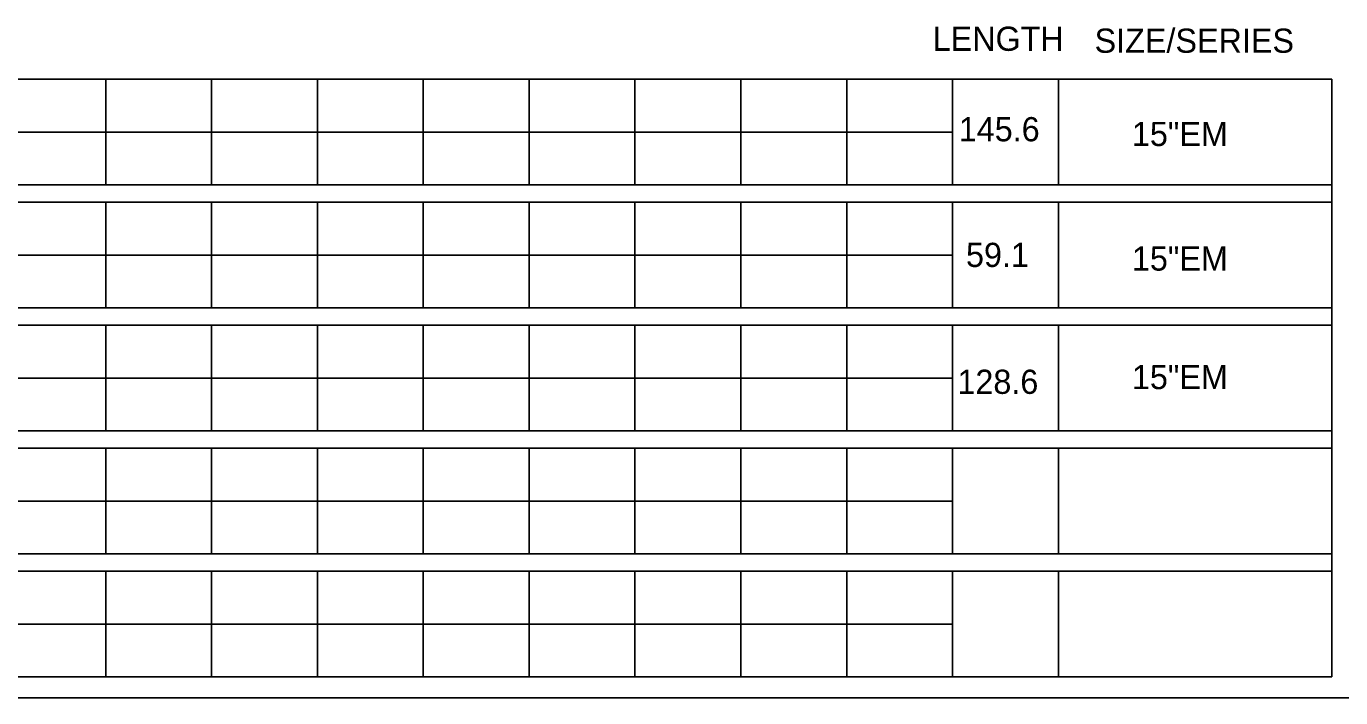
# Model space of a CAD drawing. Extents: x 10268147 to 10268469, y 2141099 to 2141204.
# Drawn here: x 10268191.41 to 10268229.47, y 2141157.19 to 2141176.62 of the extents above; entities that cross this region are included whole.
import ezdxf

# ---------------------------------------------------------------- set-up
doc = ezdxf.new("R2010")
doc.units = 0
for name, color, linetype in [('61', 7, 'Continuous'), ('GSDims', 7, 'Continuous'), ('North Arrow', 7, 'Continuous'), ('SheetLinesMisc2_dp', 7, 'Continuous'), ('TextMisc', 7, 'Continuous')]:
    doc.layers.add(name, color=color, linetype=linetype)

msp = doc.modelspace()

# ---------------------------------------------------------------- linework, layer by layer
at = {"layer": '61'}
for p, q in [((10268153.875, 2141175.094), (10268229.209, 2141175.094)), ((10268193.714, 2141175.094), (10268193.714, 2141172.034)), ((10268196.779, 2141175.094), (10268196.779, 2141172.034)), ((10268199.843, 2141175.094), (10268199.843, 2141172.034)), ((10268202.908, 2141175.094), (10268202.908, 2141172.034)), ((10268205.972, 2141175.094), (10268205.972, 2141172.034)), ((10268209.037, 2141175.094), (10268209.037, 2141172.034)), ((10268212.102, 2141175.094), (10268212.102, 2141172.034)), ((10268215.166, 2141175.094), (10268215.166, 2141172.034)), ((10268218.232, 2141175.094), (10268218.232, 2141172.034)), ((10268221.296, 2141175.094), (10268221.296, 2141172.034)), ((10268229.209, 2141157.796), (10268229.209, 2141175.094)), ((10268153.875, 2141173.564), (10268218.232, 2141173.564)), ((10268153.875, 2141172.034), (10268229.209, 2141172.034)), ((10268153.875, 2141171.535), (10268229.209, 2141171.535)), ((10268193.714, 2141171.535), (10268193.714, 2141168.475)), ((10268196.779, 2141171.535), (10268196.779, 2141168.475)), ((10268199.843, 2141171.535), (10268199.843, 2141168.475)), ((10268202.908, 2141171.535), (10268202.908, 2141168.475)), ((10268205.972, 2141171.535), (10268205.972, 2141168.475)), ((10268209.037, 2141171.535), (10268209.037, 2141168.475)), ((10268212.102, 2141171.535), (10268212.102, 2141168.475)), ((10268215.166, 2141171.535), (10268215.166, 2141168.475)), ((10268218.232, 2141171.535), (10268218.232, 2141168.475)), ((10268221.296, 2141171.535), (10268221.296, 2141168.475)), ((10268153.875, 2141170.005), (10268218.232, 2141170.005)), ((10268153.875, 2141168.475), (10268229.209, 2141168.475)), ((10268153.875, 2141167.976), (10268229.209, 2141167.976)), ((10268193.714, 2141167.976), (10268193.714, 2141164.915)), ((10268196.779, 2141167.976), (10268196.779, 2141164.915)), ((10268199.843, 2141167.976), (10268199.843, 2141164.915)), ((10268202.908, 2141167.976), (10268202.908, 2141164.915)), ((10268205.972, 2141167.976), (10268205.972, 2141164.915)), ((10268209.037, 2141167.976), (10268209.037, 2141164.915)), ((10268212.102, 2141167.976), (10268212.102, 2141164.915)), ((10268215.166, 2141167.976), (10268215.166, 2141164.915)), ((10268218.232, 2141167.976), (10268218.232, 2141164.915)), ((10268221.296, 2141167.976), (10268221.296, 2141164.915)), ((10268153.875, 2141166.445), (10268218.232, 2141166.445)), ((10268153.875, 2141164.915), (10268229.209, 2141164.915)), ((10268153.875, 2141164.416), (10268229.209, 2141164.416)), ((10268193.714, 2141164.416), (10268193.714, 2141161.355)), ((10268196.779, 2141164.416), (10268196.779, 2141161.355)), ((10268199.843, 2141164.416), (10268199.843, 2141161.355)), ((10268202.908, 2141164.416), (10268202.908, 2141161.355)), ((10268205.972, 2141164.416), (10268205.972, 2141161.355)), ((10268209.037, 2141164.416), (10268209.037, 2141161.355)), ((10268212.102, 2141164.416), (10268212.102, 2141161.355)), ((10268215.166, 2141164.416), (10268215.166, 2141161.355)), ((10268218.232, 2141164.416), (10268218.232, 2141161.355)), ((10268221.296, 2141164.416), (10268221.296, 2141161.355)), ((10268153.875, 2141162.886), (10268218.232, 2141162.886)), ((10268153.875, 2141161.355), (10268229.209, 2141161.355)), ((10268153.875, 2141160.856), (10268229.209, 2141160.856)), ((10268193.714, 2141160.856), (10268193.714, 2141157.796)), ((10268196.779, 2141160.856), (10268196.779, 2141157.796)), ((10268199.843, 2141160.856), (10268199.843, 2141157.796)), ((10268202.908, 2141160.856), (10268202.908, 2141157.796)), ((10268205.972, 2141160.856), (10268205.972, 2141157.796)), ((10268209.037, 2141160.856), (10268209.037, 2141157.796)), ((10268212.102, 2141160.856), (10268212.102, 2141157.796)), ((10268215.166, 2141160.856), (10268215.166, 2141157.796)), ((10268218.232, 2141160.856), (10268218.232, 2141157.796)), ((10268221.296, 2141160.856), (10268221.296, 2141157.796)), ((10268153.875, 2141159.327), (10268218.232, 2141159.327)), ((10268153.875, 2141157.796), (10268229.209, 2141157.796))]:
    msp.add_line(p, q, dxfattribs=at)
at = {"layer": 'SheetLinesMisc2_dp'}
msp.add_line((10268153.14, 2141157.195), (10268306.32, 2141157.195), dxfattribs=at)

# ---------------------------------------------------------------- texts
at = {"layer": 'GSDims'}
for p in [(10268223.424, 2141173.159), (10268223.424, 2141169.554), (10268223.424, 2141166.124)]:
    msp.add_text('15"EM', height=0.7, dxfattribs=at).set_placement(p)
at = {"layer": 'North Arrow'}
for s, p in [('145.6', (10268218.411, 2141173.296)), ('59.1', (10268218.62, 2141169.659)), ('128.6', (10268218.372, 2141165.987))]:
    msp.add_text(s, height=0.7, dxfattribs=at).set_placement(p)
at = {"layer": 'TextMisc'}
for s, p in [('LENGTH', (10268217.655, 2141175.914)), ('SIZE/SERIES', (10268222.343, 2141175.858))]:
    msp.add_text(s, height=0.7, dxfattribs=at).set_placement(p)

doc.saveas('drawing.dxf')
